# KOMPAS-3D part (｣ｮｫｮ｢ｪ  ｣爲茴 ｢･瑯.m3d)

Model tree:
1. Эскиз:1
2. Операция выдавливания:1
     Расстояние 1 = 2
3. Эскиз:2
4. Вырезать элемент выдавливания:1
     Расстояние 1 = 12; Угол 1 = 34
5. Эскиз:4
6. Вырезать элемент выдавливания:2
     Расстояние 1 = 10
7. Вырезать элемент выдавливания:3
     Расстояние 1 = 10
8. Эскиз:5
9. Операция выдавливания:2
     Расстояние 1 = 3; Расстояние 2 = 2
